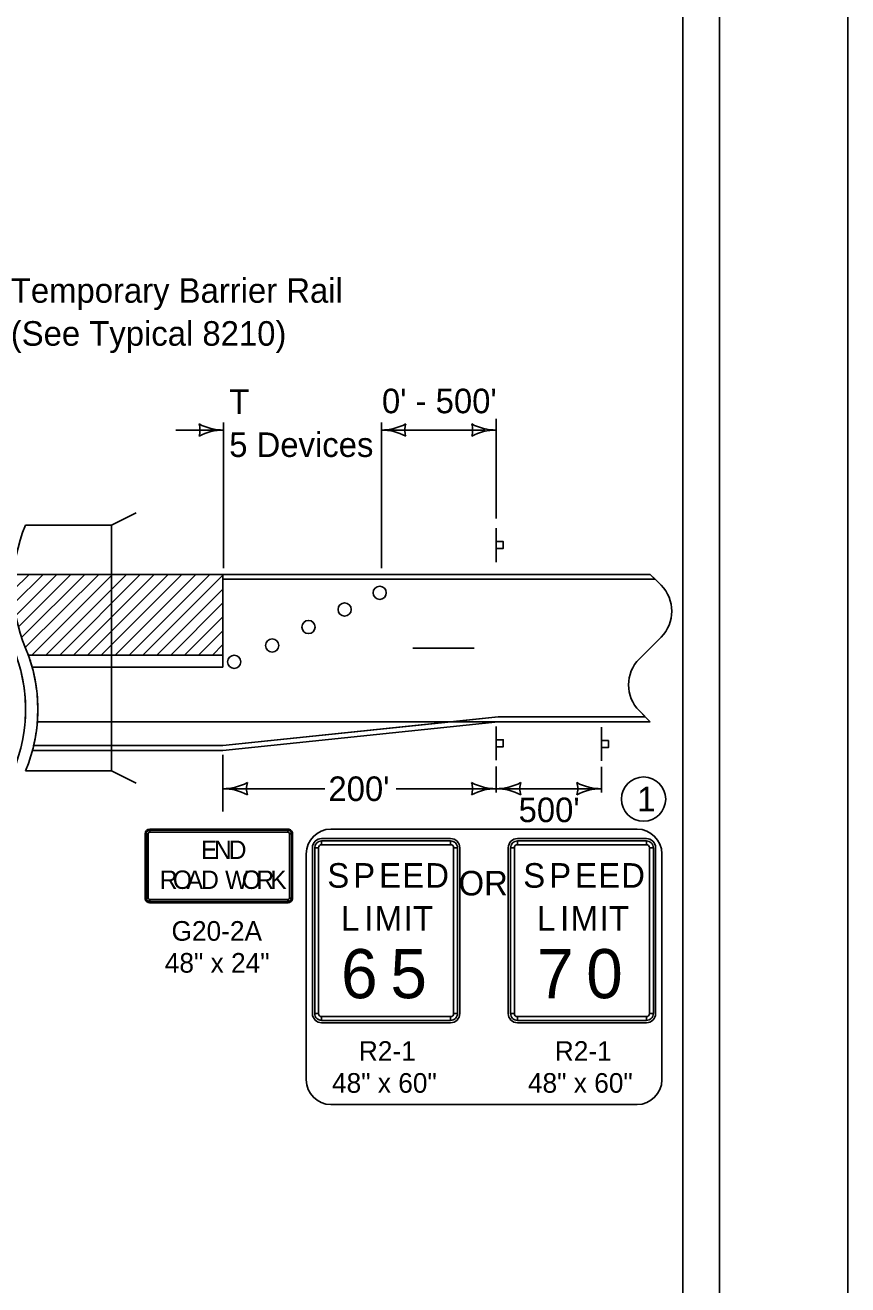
# Model space of a CAD drawing. Extents: x -2135039 to 114557, y -2139150 to -409929.
# Drawn here: x -2132365 to -2131695, y -2138196 to -2137170 of the extents above; entities that cross this region are included whole.
import ezdxf

# ---------------------------------------------------------------- set-up
doc = ezdxf.new("R2010")
doc.units = 0
for name, color, linetype in [('dsnDOTLogo', 7, 'Continuous'), ('dsnNonPlotable', 7, 'Continuous'), ('dsnStdLabel', 7, 'Continuous'), ('dsnStdLineWork', 7, 'Continuous'), ('dsnStdNote', 7, 'Continuous'), ('dsnStdShading', 7, 'Continuous'), ('Level 1', 7, 'Continuous'), ('StdDimension', 7, 'Continuous')]:
    doc.layers.add(name, color=color, linetype=linetype)

msp = doc.modelspace()

# ---------------------------------------------------------------- linework, layer by layer
at = {"layer": 'dsnDOTLogo'}
msp.add_lwpolyline([(-2135038.9, -2139150.4), (-2131694.9, -2139150.4), (-2131694.9, -2136566.4), (-2135038.9, -2136566.4)], close=True, dxfattribs=at)
at = {"layer": 'dsnNonPlotable'}
msp.add_line((-2131829.4, -2137085.9), (-2131829.4, -2138555.9), dxfattribs=at)
at = {"layer": 'dsnStdLabel'}
for p, q in [((-2131981.4, -2137579.4), (-2131981.4, -2137606.9)), ((-2132374.7, -2137629.9), (-2132361.7, -2137616.9)), ((-2132374, -2137640.5), (-2132350.4, -2137616.9)), ((-2132372.6, -2137650.4), (-2132339.1, -2137616.9)), ((-2132370.5, -2137659.7), (-2132327.8, -2137616.9)), ((-2132367.9, -2137668.4), (-2132316.5, -2137616.9)), ((-2132364.9, -2137676.6), (-2132305.1, -2137616.9)), ((-2132359.6, -2137682.6), (-2132293.8, -2137616.9)), ((-2132348.3, -2137682.6), (-2132282.5, -2137616.9)), ((-2132336.9, -2137682.6), (-2132271.2, -2137616.9)), ((-2132325.6, -2137682.6), (-2132259.9, -2137616.9)), ((-2132314.3, -2137682.6), (-2132248.6, -2137616.9)), ((-2132303, -2137682.6), (-2132237.3, -2137616.9)), ((-2132291.7, -2137682.6), (-2132226, -2137616.9)), ((-2132280.4, -2137682.6), (-2132214.6, -2137616.9)), ((-2132269.1, -2137682.6), (-2132204, -2137617.5)), ((-2132204, -2137616.9), (-2132204, -2137682.6)), ((-2132257.7, -2137682.6), (-2132204, -2137628.9)), ((-2132246.4, -2137682.6), (-2132204, -2137640.2)), ((-2132235.1, -2137682.6), (-2132204, -2137651.5)), ((-2132223.8, -2137682.6), (-2132204, -2137662.8)), ((-2132212.5, -2137682.6), (-2132204, -2137674.1)), ((-2132294.7, -2137682.6), (-2132294.7, -2137692.6)), ((-2132204, -2137692.6), (-2132204, -2137682.6)), ((-2132294.7, -2137692.6), (-2132204, -2137692.6)), ((-2132204, -2137756.4), (-2131979.8, -2137732.9)), ((-2131981.4, -2137740.8), (-2131981.4, -2137768.3)), ((-2131979.8, -2137732.9), (-2131859.9, -2137732.9)), ((-2131895.7, -2137768.8), (-2131895.7, -2137741.3)), ((-2132267.3, -2137828.1), (-2132267.3, -2137880.6)), ((-2132266.3, -2137828.1), (-2132264.8, -2137828.1)), ((-2132151, -2137824.3), (-2132263.5, -2137824.3)), ((-2132263.5, -2137826.8), (-2132263.5, -2137825.3)), ((-2132151, -2137825.3), (-2132151, -2137826.8)), ((-2132149.8, -2137828.1), (-2132148.2, -2137828.1)), ((-2132147.3, -2137880.6), (-2132147.3, -2137828.1)), ((-2132018.5, -2137832.1), (-2132123.5, -2137832.1)), ((-2131859, -2137832.1), (-2131964, -2137832.1)), ((-2132131, -2137839.6), (-2132131, -2137974.6)), ((-2132129.2, -2137839.6), (-2132126, -2137839.6)), ((-2132123.5, -2137837.1), (-2132123.5, -2137834)), ((-2132018.5, -2137834), (-2132018.5, -2137837.1)), ((-2132016, -2137839.6), (-2132012.9, -2137839.6)), ((-2132011, -2137974.6), (-2132011, -2137839.6)), ((-2131971.5, -2137839.6), (-2131971.5, -2137974.6)), ((-2131969.6, -2137839.6), (-2131966.5, -2137839.6)), ((-2131964, -2137837.1), (-2131964, -2137834)), ((-2131859, -2137834), (-2131859, -2137837.1)), ((-2131856.5, -2137839.6), (-2131853.3, -2137839.6)), ((-2131851.5, -2137974.6), (-2131851.5, -2137839.6)), ((-2132264.8, -2137880.6), (-2132266.3, -2137880.6)), ((-2132263.5, -2137883.4), (-2132263.5, -2137881.8)), ((-2132263.5, -2137884.3), (-2132151, -2137884.3)), ((-2132151, -2137881.8), (-2132151, -2137883.4)), ((-2132148.2, -2137880.6), (-2132149.8, -2137880.6)), ((-2132126, -2137974.6), (-2132129.2, -2137974.6)), ((-2132123.5, -2137980.2), (-2132123.5, -2137977.1)), ((-2132018.5, -2137977.1), (-2132018.5, -2137980.2)), ((-2132012.9, -2137974.6), (-2132016, -2137974.6)), ((-2131966.5, -2137974.6), (-2131969.6, -2137974.6)), ((-2131964, -2137980.2), (-2131964, -2137977.1)), ((-2131859, -2137977.1), (-2131859, -2137980.2)), ((-2131853.3, -2137974.6), (-2131856.5, -2137974.6)), ((-2132123.5, -2137982.1), (-2132018.5, -2137982.1)), ((-2131964, -2137982.1), (-2131859, -2137982.1))]:
    msp.add_line(p, q, dxfattribs=at)
for points in [[(-2131981.3, -2137595.8), (-2131981.3, -2137590.2), (-2131975.6, -2137590.2), (-2131975.6, -2137595.8)], [(-2131981.3, -2137757.3), (-2131981.3, -2137751.6), (-2131975.6, -2137751.6), (-2131975.6, -2137757.3)], [(-2131895.6, -2137752.3), (-2131895.6, -2137758), (-2131890, -2137758), (-2131890, -2137752.3)], [(-2132266.3, -2137828.1), (-2132266.3, -2137880.6), (-2132264.8, -2137880.6), (-2132264.8, -2137828.1), (-2132266.3, -2137828.1)], [(-2132151, -2137825.3), (-2132263.5, -2137825.3), (-2132263.5, -2137826.8), (-2132151, -2137826.8), (-2132151, -2137825.3)], [(-2132148.2, -2137880.6), (-2132148.2, -2137828.1), (-2132149.8, -2137828.1), (-2132149.8, -2137880.6), (-2132148.2, -2137880.6)], [(-2132129.2, -2137839.6), (-2132129.2, -2137974.6), (-2132126, -2137974.6), (-2132126, -2137839.6), (-2132129.2, -2137839.6)], [(-2132018.5, -2137834), (-2132123.5, -2137834), (-2132123.5, -2137837.1), (-2132018.5, -2137837.1), (-2132018.5, -2137834)], [(-2132012.9, -2137974.6), (-2132012.9, -2137839.6), (-2132016, -2137839.6), (-2132016, -2137974.6), (-2132012.9, -2137974.6)], [(-2131969.6, -2137839.6), (-2131969.6, -2137974.6), (-2131966.5, -2137974.6), (-2131966.5, -2137839.6), (-2131969.6, -2137839.6)], [(-2131859, -2137834), (-2131964, -2137834), (-2131964, -2137837.1), (-2131859, -2137837.1), (-2131859, -2137834)], [(-2131853.3, -2137974.6), (-2131853.3, -2137839.6), (-2131856.5, -2137839.6), (-2131856.5, -2137974.6), (-2131853.3, -2137974.6)], [(-2132263.5, -2137883.4), (-2132151, -2137883.4), (-2132151, -2137881.8), (-2132263.5, -2137881.8), (-2132263.5, -2137883.4)], [(-2132123.5, -2137980.2), (-2132018.5, -2137980.2), (-2132018.5, -2137977.1), (-2132123.5, -2137977.1), (-2132123.5, -2137980.2)], [(-2131964, -2137980.2), (-2131859, -2137980.2), (-2131859, -2137977.1), (-2131964, -2137977.1), (-2131964, -2137980.2)]]:
    msp.add_lwpolyline(points, close=True, dxfattribs=at)
for points in [[(-2132204, -2137682.6), (-2132212.5, -2137682.6), (-2132223.8, -2137682.6), (-2132235.1, -2137682.6), (-2132246.4, -2137682.6), (-2132257.7, -2137682.6), (-2132269.1, -2137682.6), (-2132280.4, -2137682.6), (-2132291.7, -2137682.6), (-2132294.7, -2137682.6)], [(-2132116, -2137824.3), (-2131866.5, -2137824.3)], [(-2132136.2, -2138028.6), (-2132136.2, -2137844.5)], [(-2131846.3, -2137844.5), (-2131846.3, -2138028.6)], [(-2131866.5, -2138048.7), (-2132116, -2138048.7)]]:
    msp.add_lwpolyline(points, dxfattribs=at)
for centre in [(-2132076.2, -2137631.9), (-2132076.2, -2137631.9), (-2132104.8, -2137645.5), (-2132104.8, -2137645.5), (-2132134.2, -2137659.8), (-2132134.2, -2137659.8), (-2132163.8, -2137674.9), (-2132163.8, -2137674.9), (-2132194.7, -2137688.1), (-2132194.7, -2137688.1)]:
    msp.add_circle(centre, 5.37, dxfattribs=at)
for centre, radius, start, end in [((-2132263.5, -2137828.1), 3.75, 90.0002, 179.9998), ((-2132263.5, -2137828.1), 2.81, 90.0002, 179.9998), ((-2132263.5, -2137828.1), 1.25, 90.0002, 179.9998), ((-2132151, -2137828.1), 3.75, 0, 90.0002), ((-2132151, -2137828.1), 2.81, 0, 90.0002), ((-2132151, -2137828.1), 1.25, 0, 90.0002), ((-2132116, -2137844.5), 20.1, 90, 180), ((-2132123.5, -2137839.6), 7.5, 90.0002, 179.9998), ((-2132018.5, -2137839.6), 7.5, 0, 90.0002), ((-2131964, -2137839.6), 7.5, 90.0002, 179.9998), ((-2131866.5, -2137844.5), 20.1, 0, 90), ((-2131859, -2137839.6), 7.5, 0, 90.0002), ((-2132123.5, -2137839.6), 5.62, 90.0002, 179.9998), ((-2132123.5, -2137839.6), 2.5, 90.0002, 179.9998), ((-2132018.5, -2137839.6), 5.62, 0, 90.0002), ((-2132018.5, -2137839.6), 2.5, 0, 90.0002), ((-2131964, -2137839.6), 5.62, 90.0002, 179.9998), ((-2131964, -2137839.6), 2.5, 90.0002, 179.9998), ((-2131859, -2137839.6), 5.62, 0, 90.0002), ((-2131859, -2137839.6), 2.5, 0, 90.0002), ((-2132263.5, -2137880.6), 3.75, 179.9998, 270.0001), ((-2132263.5, -2137880.6), 2.81, 179.9998, 270.0001), ((-2132263.5, -2137880.6), 1.25, 179.9998, 270.0001), ((-2132151, -2137880.6), 3.75, 270.0001, 0.0003), ((-2132151, -2137880.6), 2.81, 270.0001, 0.0003), ((-2132151, -2137880.6), 1.25, 270.0001, 0.0003), ((-2132123.5, -2137974.6), 7.5, 179.9998, 270.0001), ((-2132123.5, -2137974.6), 5.62, 179.9998, 270.0001), ((-2132123.5, -2137974.6), 2.5, 179.9998, 270.0001), ((-2132018.5, -2137974.6), 7.5, 270.0001, 0.0003), ((-2132018.5, -2137974.6), 5.62, 270.0001, 0.0003), ((-2132018.5, -2137974.6), 2.5, 270.0001, 0.0003), ((-2131964, -2137974.6), 7.5, 179.9998, 270.0001), ((-2131964, -2137974.6), 5.62, 179.9998, 270.0001), ((-2131964, -2137974.6), 2.5, 179.9998, 270.0001), ((-2131859, -2137974.6), 7.5, 270.0001, 0.0003), ((-2131859, -2137974.6), 5.62, 270.0001, 0.0003), ((-2131859, -2137974.6), 2.5, 270.0001, 0.0003), ((-2132116, -2138028.6), 20.1, 180, 270), ((-2131866.5, -2138028.6), 20.1, 270, 0)]:
    msp.add_arc(centre, radius, start, end, dxfattribs=at)
at = {"layer": 'dsnStdLineWork'}
for p, q in [((-2132294.7, -2137576.9), (-2132274.7, -2137566.9)), ((-2131847.1, -2137625.7), (-2131855.9, -2137616.9)), ((-2131864.7, -2137685.7), (-2131847.1, -2137668.1)), ((-2132362.5, -2137682.6), (-2132204, -2137682.6)), ((-2132204, -2137682.6), (-2132204, -2137692.6)), ((-2132204, -2137692.6), (-2132359.3, -2137692.6)), ((-2131855.9, -2137736.9), (-2131864.7, -2137728.1)), ((-2132355.1, -2137736.9), (-2131979.8, -2137736.9)), ((-2132204, -2137756.4), (-2131979.8, -2137732.9)), ((-2132358.1, -2137756.4), (-2132204, -2137756.4)), ((-2132364.7, -2137776.9), (-2132294.7, -2137776.9)), ((-2132294.7, -2137776.9), (-2132274.7, -2137786.9))]:
    msp.add_line(p, q, dxfattribs=at)
for points in [[(-2132294.7, -2137776.9), (-2132294.7, -2137576.9), (-2132364.7, -2137576.9)], [(-2132204, -2137620.9), (-2131851.9, -2137620.9)], [(-2132049.3, -2137676.9), (-2131999.3, -2137676.9)], [(-2132049.3, -2137676.9), (-2131999.3, -2137676.9)], [(-2132362.5, -2137682.6), (-2132349.4, -2137682.6)], [(-2132346.3, -2137692.6), (-2132359.3, -2137692.6)], [(-2131979.8, -2137732.9), (-2131859.9, -2137732.9)]]:
    msp.add_lwpolyline(points, dxfattribs=at)
for centre, radius, start, end in [((-2132244.7, -2137626.9), 130, 157.3801, 202.6199), ((-2131868.3, -2137646.9), 30, 315, 45), ((-2132494.7, -2137726.9), 130, 337.3801, 22.6199), ((-2132484.7, -2137726.9), 130, 337.3801, 22.6199), ((-2131843.5, -2137706.9), 30, 135, 225)]:
    msp.add_arc(centre, radius, start, end, dxfattribs=at)
at = {"layer": 'dsnStdNote'}
msp.add_circle((-2131861.3, -2137799.9), 18, dxfattribs=at)
at = {"layer": 'dsnStdShading'}
for p, q in [((-2132374.3, -2137616.9), (-2131855.9, -2137616.9)), ((-2131855.9, -2137616.9), (-2132204, -2137616.9)), ((-2132204, -2137616.9), (-2132204, -2137620.9)), ((-2131851.9, -2137620.9), (-2131855.9, -2137616.9)), ((-2132204, -2137620.9), (-2131851.9, -2137620.9)), ((-2131851.9, -2137620.9), (-2132204, -2137620.9)), ((-2132204, -2137620.9), (-2132204, -2137628.9)), ((-2131847.1, -2137625.7), (-2131851.9, -2137620.9)), ((-2132204, -2137628.9), (-2132204, -2137640.2)), ((-2132204, -2137640.2), (-2132204, -2137651.5)), ((-2131864.7, -2137685.7), (-2131847.1, -2137668.1)), ((-2132294.7, -2137692.6), (-2132294.7, -2137682.6)), ((-2132204, -2137682.6), (-2132204, -2137692.6)), ((-2132359.3, -2137692.6), (-2132346.3, -2137692.6)), ((-2132346.3, -2137692.6), (-2132294.7, -2137692.6)), ((-2132294.7, -2137736.9), (-2132294.7, -2137692.6)), ((-2132204, -2137692.6), (-2132294.7, -2137692.6)), ((-2132294.7, -2137692.6), (-2132294.7, -2137736.9)), ((-2131859.9, -2137732.9), (-2131864.7, -2137728.1)), ((-2132294.7, -2137736.9), (-2132355.1, -2137736.9)), ((-2132355.1, -2137736.9), (-2132294.7, -2137736.9)), ((-2132061.6, -2137736.9), (-2132294.7, -2137736.9)), ((-2132294.7, -2137736.9), (-2132294.7, -2137756.4)), ((-2132294.7, -2137756.4), (-2132294.7, -2137736.9)), ((-2132294.7, -2137736.9), (-2132017.9, -2137736.9)), ((-2132204, -2137760.4), (-2131979.8, -2137736.9)), ((-2132204, -2137756.4), (-2132017.9, -2137736.9)), ((-2132204, -2137760.4), (-2131979.8, -2137736.9)), ((-2132017.9, -2137736.9), (-2132204, -2137756.4)), ((-2132061.6, -2137736.9), (-2131855.9, -2137736.9)), ((-2132017.9, -2137736.9), (-2132061.6, -2137736.9)), ((-2131979.8, -2137732.9), (-2132017.9, -2137736.9)), ((-2132017.9, -2137736.9), (-2131979.8, -2137732.9)), ((-2131979.8, -2137736.9), (-2132017.9, -2137736.9)), ((-2132017.9, -2137736.9), (-2131855.9, -2137736.9)), ((-2131859.9, -2137732.9), (-2131979.8, -2137732.9)), ((-2131979.8, -2137732.9), (-2131859.9, -2137732.9)), ((-2131855.9, -2137736.9), (-2131859.9, -2137732.9)), ((-2132359.1, -2137760.4), (-2132294.7, -2137760.4)), ((-2132359.1, -2137760.4), (-2132204, -2137760.4)), ((-2132359.1, -2137760.4), (-2132346.1, -2137760.4)), ((-2132358.1, -2137756.4), (-2132345.1, -2137756.4)), ((-2132345.1, -2137756.4), (-2132358.1, -2137756.4)), ((-2132345.1, -2137756.4), (-2132294.7, -2137756.4)), ((-2132294.7, -2137756.4), (-2132345.1, -2137756.4)), ((-2132294.7, -2137756.4), (-2132204, -2137756.4)), ((-2132204, -2137756.4), (-2132294.7, -2137756.4)), ((-2132294.7, -2137756.4), (-2132294.7, -2137760.4)), ((-2132294.7, -2137760.4), (-2132294.7, -2137756.4)), ((-2132294.7, -2137760.4), (-2132204, -2137760.4))]:
    msp.add_line(p, q, dxfattribs=at)
for points in [[(-2131851.9, -2137620.9), (-2131851.9, -2137620.9)], [(-2131851.9, -2137620.9), (-2131851.9, -2137620.9)], [(-2132204, -2137651.5), (-2132204, -2137662.8), (-2132204, -2137674.1), (-2132204, -2137682.6)], [(-2132294.7, -2137682.6), (-2132303, -2137682.6), (-2132314.3, -2137682.6), (-2132325.6, -2137682.6), (-2132336.9, -2137682.6), (-2132348.3, -2137682.6), (-2132349.4, -2137682.6), (-2132359.6, -2137682.6), (-2132362.5, -2137682.6)], [(-2132294.7, -2137692.6), (-2132346.3, -2137692.6), (-2132359.3, -2137692.6)], [(-2132061.6, -2137736.9), (-2132061.6, -2137736.9)], [(-2131859.9, -2137732.9), (-2131859.9, -2137732.9)], [(-2131859.9, -2137732.9), (-2131859.9, -2137732.9)]]:
    msp.add_lwpolyline(points, dxfattribs=at)
for centre, radius, start, end in [((-2131868.3, -2137646.9), 30, 315, 45), ((-2132484.7, -2137726.9), 130, 15.2832, 19.9082), ((-2131843.5, -2137706.9), 30, 135, 225), ((-2132494.7, -2137726.9), 130, 355.5883, 15.2823), ((-2132484.7, -2137726.9), 130, 355.5892, 15.2832), ((-2132484.7, -2137726.9), 130, 346.8826, 355.5892), ((-2132484.7, -2137726.9), 130, 345.0654, 346.8826)]:
    msp.add_arc(centre, radius, start, end, dxfattribs=at)
at = {"layer": 'Level 1'}
msp.add_lwpolyline([(-2134934.4, -2137035.9), (-2131799.4, -2137035.9), (-2131799.4, -2139045.9), (-2134934.4, -2139045.9)], close=True, dxfattribs=at)
at = {"layer": 'StdDimension'}
for p, q in [((-2132203.4, -2137611.9), (-2132203.4, -2137493.2)), ((-2132074.9, -2137611.9), (-2132074.9, -2137493.2)), ((-2131981.4, -2137571.4), (-2131981.4, -2137490.2)), ((-2132242.2, -2137499.4), (-2132203.4, -2137499.4)), ((-2132074.9, -2137499.4), (-2131990.2, -2137499.4)), ((-2132204, -2137763.8), (-2132204, -2137810.1)), ((-2131981.4, -2137794.7), (-2131981.4, -2137773.4)), ((-2131895.7, -2137794.7), (-2131895.7, -2137773.7)), ((-2132121, -2137791.5), (-2132204, -2137791.5)), ((-2131981.4, -2137791.5), (-2132062.7, -2137791.5)), ((-2131981.4, -2137791.5), (-2131895.7, -2137791.5))]:
    msp.add_line(p, q, dxfattribs=at)
for centre, radius, start, end in [((-2132239, -2137499.4), 16.4, 342.2666, 17.7333), ((-2132203.4, -2137456.9), 42.5, 241.9275, 270), ((-2132075, -2137456.9), 42.5, 270, 298.0725), ((-2132039.4, -2137499.4), 16.4, 162.2666, 197.7334), ((-2132016.9, -2137499.4), 16.4, 342.2666, 17.7333), ((-2131981.3, -2137456.9), 42.5, 241.9275, 270), ((-2132203.4, -2137541.9), 42.5, 90, 118.0725), ((-2132075, -2137541.9), 42.5, 61.9275, 90), ((-2131981.3, -2137541.9), 42.5, 90, 118.0725), ((-2132204, -2137749), 42.5, 270, 298.0725), ((-2132204, -2137834), 42.5, 61.9275, 90), ((-2132168.3, -2137791.5), 16.4, 162.2666, 197.7334), ((-2132017, -2137791.5), 16.4, 342.2666, 17.7334), ((-2131981.4, -2137749), 42.5, 241.9275, 270), ((-2131981.4, -2137834), 42.5, 90, 118.0725), ((-2131981.4, -2137749), 42.5, 270, 298.0725), ((-2131981.4, -2137834), 42.5, 61.9275, 90), ((-2131945.7, -2137791.5), 16.4, 162.2666, 197.7334), ((-2131931.3, -2137791.5), 16.4, 342.2666, 17.7333), ((-2131895.7, -2137749), 42.5, 241.9275, 270), ((-2131895.7, -2137834), 42.5, 90, 118.0725)]:
    msp.add_arc(centre, radius, start, end, dxfattribs=at)

# ---------------------------------------------------------------- texts
at = {"layer": 'dsnStdLabel'}
for s, height, p in [('E', 15, (-2132221.9, -2137848.7)), ('N', 15, (-2132211.3, -2137848.7)), ('D', 15, (-2132199.2, -2137848.7)), ('S', 20, (-2132118.9, -2137872.1)), ('P', 20, (-2132097.8, -2137872.1)), ('E', 20, (-2132076.7, -2137872.1)), ('E', 20, (-2132057.9, -2137872.1)), ('D', 20, (-2132039.1, -2137872.1)), ('S', 20, (-2131959.3, -2137872.1)), ('P', 20, (-2131938.2, -2137872.1)), ('E', 20, (-2131917.1, -2137872.1)), ('E', 20, (-2131898.3, -2137872.1)), ('D', 20, (-2131879.5, -2137872.1)), ('R', 15, (-2132255.4, -2137873.1)), ('O', 15, (-2132244.7, -2137873.1)), ('A', 15, (-2132233.5, -2137873.1)), ('D', 15, (-2132221.7, -2137873.1)), ('W', 15, (-2132202.2, -2137873.1)), ('O', 15, (-2132188.5, -2137873.1)), ('R', 15, (-2132176.7, -2137873.1)), ('K', 15, (-2132165.4, -2137873.1)), ('OR', 20, (-2132012, -2137878.4)), ('L', 20, (-2132107.7, -2137907.1)), ('I', 20, (-2132088.9, -2137907.1)), ('M', 20, (-2132080.3, -2137907.1)), ('I', 20, (-2132056.7, -2137907.1)), ('T', 20, (-2132049.1, -2137907.1)), ('L', 20, (-2131948.1, -2137907.1)), ('I', 20, (-2131929.3, -2137907.1)), ('M', 20, (-2131920.7, -2137907.1)), ('I', 20, (-2131897.1, -2137907.1)), ('T', 20, (-2131889.5, -2137907.1)), ('G20-2A', 16, (-2132245.8, -2137915.3)), ('48" x 24"', 16, (-2132251.3, -2137941.3)), ('6', 40, (-2132107.7, -2137962.1)), ('5', 40, (-2132067.5, -2137962.1)), ('7', 40, (-2131948.1, -2137962.1)), ('0', 40, (-2131908, -2137962.1)), ('R2-1', 16, (-2132093.2, -2138013.1)), ('R2-1', 16, (-2131933.6, -2138013.1)), ('48" x 60"', 16, (-2132115.1, -2138039.1)), ('48" x 60"', 16, (-2131955.5, -2138039.1))]:
    msp.add_text(s, height=height, dxfattribs=at).set_placement(p)
at = {"layer": 'dsnStdNote'}
msp.add_text('1', height=20, dxfattribs=at).set_placement((-2131866.5, -2137809.9))
at = {"layer": 'StdDimension'}
for s, p in [('Temporary Barrier Rail', (-2132376.7, -2137395.7)), ('(See Typical 8210)', (-2132376.7, -2137430.7)), ('T', (-2132198.8, -2137486.3)), ("0' - 500'", (-2132074.4, -2137485.7)), ('5 Devices', (-2132198.8, -2137521.3)), ("200'", (-2132118, -2137801.5)), ("500'", (-2131963.1, -2137818.7))]:
    msp.add_text(s, height=20, dxfattribs=at).set_placement(p)

doc.saveas('drawing.dxf')
